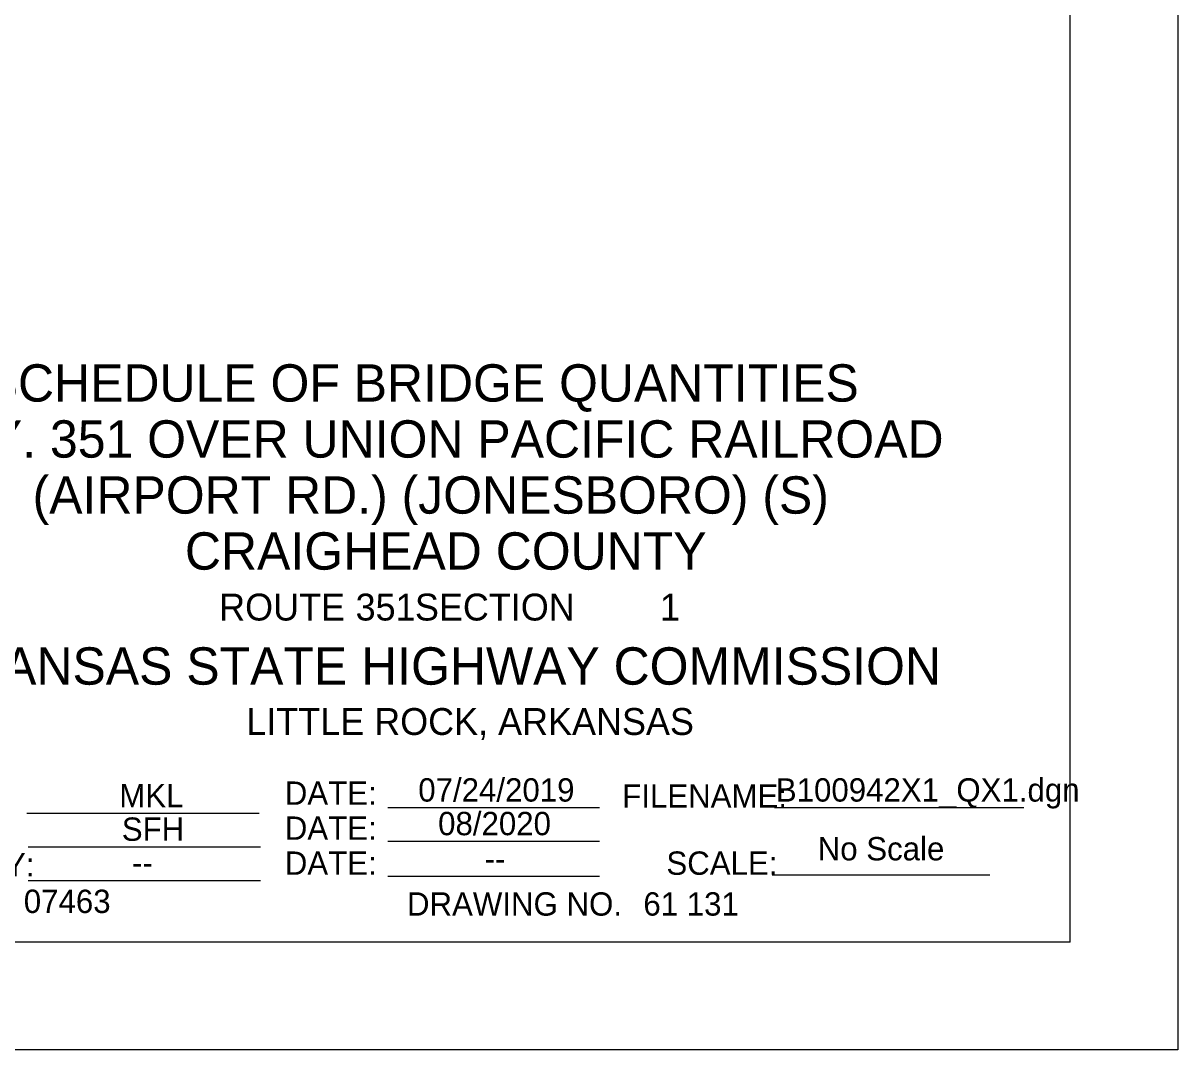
# Model space of a CAD drawing. Extents: x -129 to 14744569, y -102 to 1829048.
# Drawn here: x -101.32 to -95.13, y -101.98 to -96.48 of the extents above; entities that cross this region are included whole.
import ezdxf

# ---------------------------------------------------------------- set-up
doc = ezdxf.new("R2010")
doc.units = 0
for name, color, linetype in [('B_Copy In', 7, 'Continuous'), ('B_County and Route', 7, 'Continuous'), ('B_Text', 7, 'Continuous'), ('B_Title Text', 7, 'Continuous'), ('R_Border', 7, 'Continuous')]:
    doc.layers.add(name, color=color, linetype=linetype)

msp = doc.modelspace()

# ---------------------------------------------------------------- linework, layer by layer
at = {"layer": 'B_Text'}
for p, q in [((-101.2977, -100.7114), (-100.0545, -100.7114)), ((-99.3645, -100.6814), (-98.2305, -100.6814)), ((-97.2945, -100.6814), (-95.9584, -100.6814)), ((-99.3645, -100.8614), (-98.2305, -100.8614)), ((-99.3645, -100.8614), (-98.2305, -100.8614)), ((-101.2905, -100.8914), (-100.0473, -100.8914)), ((-99.3645, -101.0489), (-98.2305, -101.0489)), ((-97.3069, -101.0414), (-96.1413, -101.0414)), ((-101.2905, -101.0714), (-100.0473, -101.0714))]:
    msp.add_line(p, q, dxfattribs=at)
at = {"layer": 'R_Border'}
for q in [(-95.7105, -80.5562), (-127.6177, -101.4026)]:
    msp.add_line((-95.7105, -101.4026), q, dxfattribs=at)
msp.add_lwpolyline([(-129.1337, -79.9794), (-95.1337, -79.9794), (-95.1337, -101.9794), (-129.1337, -101.9794)], close=True, dxfattribs=at)

# ---------------------------------------------------------------- texts
at = {"layer": 'B_Copy In'}
for s, height, p in [('SCHEDULE OF BRIDGE QUANTITIES', 0.2, (-101.5238, -98.507)), ('HWY. 351 OVER UNION PACIFIC RAILROAD', 0.2, (-101.9466, -98.807)), ('(AIRPORT RD.) (JONESBORO) (S)', 0.2, (-101.2671, -99.107)), ('MKL', 0.125, (-100.8029, -100.6794)), ('07/24/2019', 0.125, (-99.2017, -100.6494)), ('B100942X1_QX1.dgn', 0.125, (-97.2868, -100.6494)), ('SFH', 0.125, (-100.7894, -100.8594)), ('08/2020', 0.125, (-99.0954, -100.8294)), ('No Scale', 0.125, (-97.0627, -100.9642)), ('--', 0.125, (-100.7343, -101.0394)), ('--', 0.125, (-98.847, -101.0169)), ('07463', 0.125, (-101.3142, -101.246)), ('61 131', 0.125, (-97.9963, -101.26))]:
    msp.add_text(s, height=height, dxfattribs=at).set_placement(p)
at = {"layer": 'B_County and Route'}
for s, height, p in [('CRAIGHEAD COUNTY', 0.2, (-100.4513, -99.407)), (' 351   ', 0.144, (-99.5909, -99.6794)), ('1', 0.144, (-97.9074, -99.6794))]:
    msp.add_text(s, height=height, dxfattribs=at).set_placement(p)
at = {"layer": 'B_Text'}
for s, p in [('DATE:', (-99.9165, -100.6664)), ('FILENAME:', (-98.1095, -100.6814)), ('DATE:', (-99.9165, -100.8539)), ('DESIGNED BY:', (-102.4461, -101.0499)), ('DATE:', (-99.9165, -101.0414)), ('SCALE:', (-97.8729, -101.0414)), ('DRAWING NO.', (-99.2622, -101.2602))]:
    msp.add_text(s, height=0.125, dxfattribs=at).set_placement(p)
at = {"layer": 'B_Title Text'}
for s, height, p in [('ROUTE       SECTION ', 0.144, (-100.2681, -99.6794)), ('ARKANSAS STATE HIGHWAY COMMISSION', 0.2, (-101.9749, -100.023)), ('LITTLE ROCK, ARKANSAS', 0.144, (-100.1225, -100.2923))]:
    msp.add_text(s, height=height, dxfattribs=at).set_placement(p)

doc.saveas('drawing.dxf')
